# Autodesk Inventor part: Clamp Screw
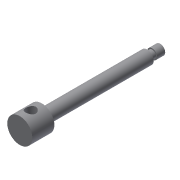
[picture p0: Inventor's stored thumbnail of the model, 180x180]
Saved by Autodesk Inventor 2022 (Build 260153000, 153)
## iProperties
Created: 2002-02
Part Number: Clamp Screw
Document SubType Name: Modeling
Designer: ***
Density: 1 g/cm^3
Material: Generic
Appearance: Default
Control State: 0
Master: False
Checked Out: False
Shininess: 77.0
Length Units: 11269
Angle Units: 11279
Time Units: 11290
Mass Units: 11283
Length Display Precision: 3
Angle Display Precision: 2
Density: 0.0
Volumn: 0.0
Area: 0.0
PropertySet Name: Model Information
Author: ***
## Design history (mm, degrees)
sketch "Sketch1"
  geometry: L1 (0, 140)-(5, 140); L2 (5, 140)-(5, 132); L3 (5, 132)-(4, 132); L4 (4, 132)-(4, 127); L5 (4, 127)-(6.5, 127); L6 (6.5, 127)-(6.5, 25); L7 (6.5, 25)-(4, 25); L8 (4, 25)-(4, 22); L9 (4, 22)-(12.5, 22); L10 (12.5, 22)-(12.5, 0); L11 (12.5, 0)-(0, 0); L12 (0, 0)-(0, 140)
  constraints: 24 end point, 10 parallel, 1 horizontal, 1 perpendicular
  dimensions: "d0" = 10 diameter of L2 L12; "d1" = 8 diameter of L4 L12; "d2" = 13 diameter of L6 L12; "d3" = 8 diameter of L7.end L12; "d4" = 25 diameter of L10 L12; "d5" = 3 distance from line of L7.end L9; "d6" = 8 distance of L1.end L2.end; "d7" = 13 vertical distance of L1.end L5.end; "d8" = 22 distance of L9.end L10.end; "d10" = 102 distance of L5.end L6.end
revolve "Revolution1" sketch "Sketch1" stored, may be unused: angle "d11" = 90 deg
sketch "Sketch3"
  geometry: L1 (-12.5, 0)-(12.5, 0) reference; C1 r 5 at (-0.113, 11)
  constraints: 1 centre point
  dimensions: "d13" = 10 diameter of C1; "d14" = 11 distance from line of L1 C1.centre
extrude "Extrusion1" cut sketch "Sketch3" extent not by distance; stored distance "d15" = 10; taper "d16" = 0 deg
body "Solid1"
